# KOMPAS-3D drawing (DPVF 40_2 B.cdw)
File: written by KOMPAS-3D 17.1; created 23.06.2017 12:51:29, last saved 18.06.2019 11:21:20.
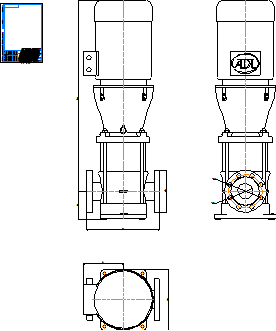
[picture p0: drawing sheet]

Sheet 1: A4, portrait

Title block, sheet 1: name: DPVF 40_2 B; material: Внимание! Данный продукт является объектом авторского права ООО «Торговый Дом АДЛ». / Запрещается изменение, копирование, распространение / (в том числе путем копирования на другие сайты и ресурсы в Интернете) / или любое иное использование информации и объектов без предварительного / согласия правообладателя (ООО «Торговый Дом АДЛ»).; scale: 1:1; sheets: 1; organisation: ООО "Торговый дом АДЛ"; sheet format: A4; stored path: C:\Клочков АВ\Насосы\DP PAMS\DPVF 40\Компас 2d\DPVF 40_2 B.cdw

Views: Спереди 1
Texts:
  Клочков АВ
  ООО АДЛ ГРУПП
Dimensions and other numbers on the sheet: 365; 197; 209,6; 947,5; 140; 168,1; 76,2; 306; 1:1; 1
